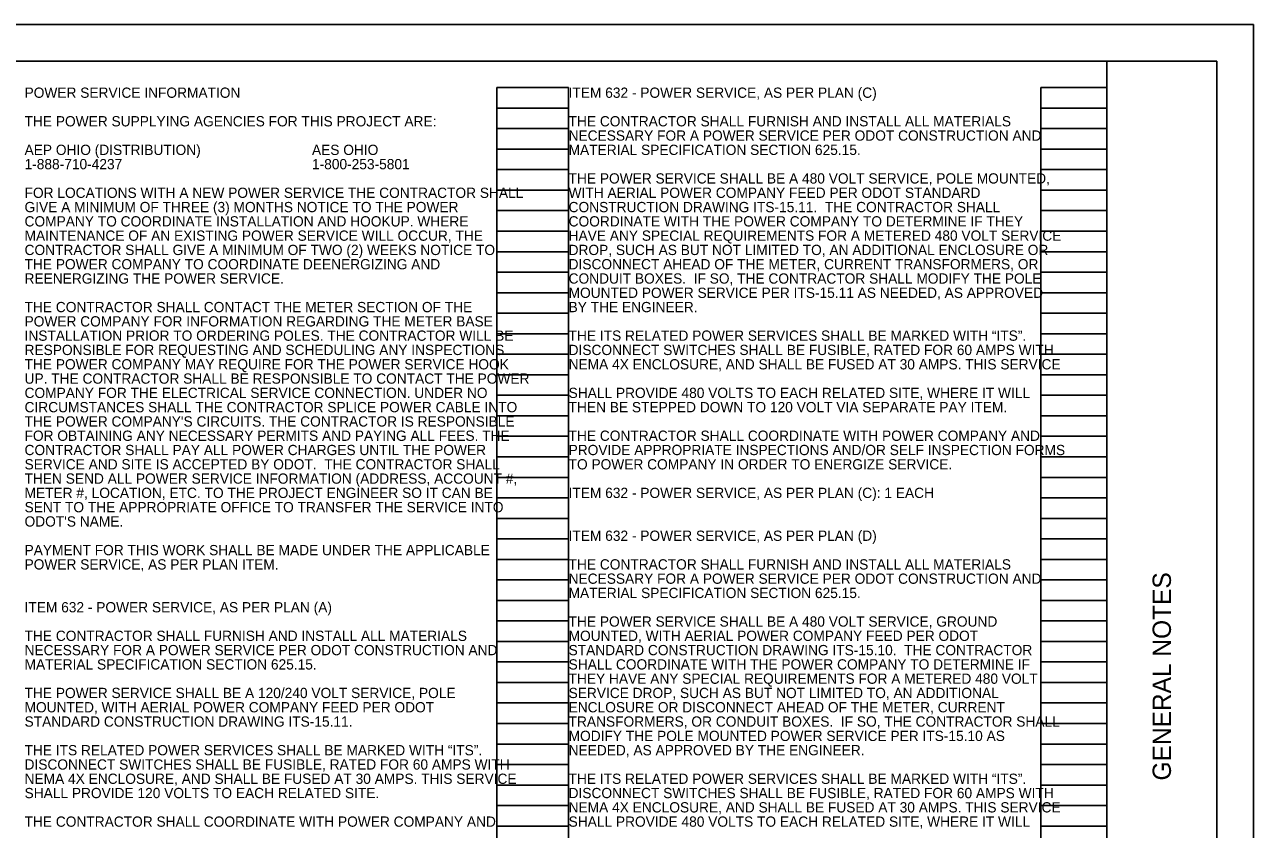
# Model space of a CAD drawing. Extents: x 0 to 34, y 0 to 22.
# Drawn here: x 17.24 to 34, y 11.01 to 22 of the extents above; entities that cross this region are included whole.
import ezdxf

# ---------------------------------------------------------------- set-up
doc = ezdxf.new("R2010")
doc.units = 0
for name, color, linetype in [('SH_Border', 7, 'Continuous'), ('SH_Cut_Line', 7, 'Continuous'), ('SH_Data', 7, 'Continuous'), ('SH_Text', 7, 'Continuous')]:
    doc.layers.add(name, color=color, linetype=linetype)

msp = doc.modelspace()

# ---------------------------------------------------------------- linework, layer by layer
at = {"layer": 'SH_Border'}
msp.add_line((32, 0.5), (32, 21.5), dxfattribs=at)
msp.add_lwpolyline([(1.5, 21.5), (33.5, 21.5), (33.5, 0.5), (1.5, 0.5)], close=True, dxfattribs=at)
at = {"layer": 'SH_Cut_Line'}
msp.add_lwpolyline([(0, 0), (34, 0), (34, 22), (0, 22)], close=True, dxfattribs=at)
at = {"layer": 'SH_Data'}
for p, q in [((23.68, 0.98), (23.68, 21.14)), ((23.68, 21.14), (24.66, 21.14)), ((24.66, 0.98), (24.66, 21.14)), ((31.1, 0.98), (31.1, 21.14)), ((31.1, 21.14), (32, 21.14)), ((32, 0.98), (32, 21.14)), ((23.68, 20.86), (24.66, 20.86)), ((31.1, 20.86), (32, 20.86)), ((23.68, 20.58), (24.66, 20.58)), ((31.1, 20.58), (32, 20.58)), ((23.68, 20.3), (24.66, 20.3)), ((31.1, 20.3), (32, 20.3)), ((23.68, 20.02), (24.66, 20.02)), ((31.1, 20.02), (32, 20.02)), ((23.68, 19.74), (24.66, 19.74)), ((31.1, 19.74), (32, 19.74)), ((23.68, 19.46), (24.66, 19.46)), ((31.1, 19.46), (32, 19.46)), ((23.68, 19.18), (24.66, 19.18)), ((31.1, 19.18), (32, 19.18)), ((23.68, 18.9), (24.66, 18.9)), ((31.1, 18.9), (32, 18.9)), ((23.68, 18.62), (24.66, 18.62)), ((31.1, 18.62), (32, 18.62)), ((23.68, 18.34), (24.66, 18.34)), ((31.1, 18.34), (32, 18.34)), ((23.68, 18.06), (24.66, 18.06)), ((31.1, 18.06), (32, 18.06)), ((23.68, 17.78), (24.66, 17.78)), ((31.1, 17.78), (32, 17.78)), ((23.68, 17.5), (24.66, 17.5)), ((31.1, 17.5), (32, 17.5)), ((23.68, 17.22), (24.66, 17.22)), ((31.1, 17.22), (32, 17.22)), ((23.68, 16.94), (24.66, 16.94)), ((31.1, 16.94), (32, 16.94)), ((23.68, 16.66), (24.66, 16.66)), ((31.1, 16.66), (32, 16.66)), ((23.68, 16.38), (24.66, 16.38)), ((31.1, 16.38), (32, 16.38)), ((23.68, 16.1), (24.66, 16.1)), ((31.1, 16.1), (32, 16.1)), ((23.68, 15.82), (24.66, 15.82)), ((31.1, 15.82), (32, 15.82)), ((23.68, 15.54), (24.66, 15.54)), ((31.1, 15.54), (32, 15.54)), ((23.68, 15.26), (24.66, 15.26)), ((31.1, 15.26), (32, 15.26)), ((23.68, 14.98), (24.66, 14.98)), ((31.1, 14.98), (32, 14.98)), ((23.68, 14.7), (24.66, 14.7)), ((31.1, 14.7), (32, 14.7)), ((23.68, 14.42), (24.66, 14.42)), ((31.1, 14.42), (32, 14.42)), ((23.68, 14.14), (24.66, 14.14)), ((31.1, 14.14), (32, 14.14)), ((23.68, 13.86), (24.66, 13.86)), ((31.1, 13.86), (32, 13.86)), ((23.68, 13.58), (24.66, 13.58)), ((31.1, 13.58), (32, 13.58)), ((23.68, 13.3), (24.66, 13.3)), ((31.1, 13.3), (32, 13.3)), ((23.68, 13.02), (24.66, 13.02)), ((31.1, 13.02), (32, 13.02)), ((23.68, 12.74), (24.66, 12.74)), ((31.1, 12.74), (32, 12.74)), ((23.68, 12.46), (24.66, 12.46)), ((31.1, 12.46), (32, 12.46)), ((23.68, 12.18), (24.66, 12.18)), ((31.1, 12.18), (32, 12.18)), ((23.68, 11.9), (24.66, 11.9)), ((31.1, 11.9), (32, 11.9)), ((23.68, 11.62), (24.66, 11.62)), ((31.1, 11.62), (32, 11.62)), ((23.68, 11.34), (24.66, 11.34)), ((31.1, 11.34), (32, 11.34)), ((23.68, 11.06), (24.66, 11.06)), ((31.1, 11.06), (32, 11.06))]:
    msp.add_line(p, q, dxfattribs=at)

# ---------------------------------------------------------------- texts
msp.add_text('GENERAL NOTES', height=0.25, rotation=90, dxfattribs=at).set_placement((32.875, 11.682))
at = {"layer": 'SH_Text'}
for s, p in [('POWER SERVICE INFORMATION', (17.24, 21)), ('ITEM 632 - POWER SERVICE, AS PER PLAN (C)', (24.66, 21)), ('THE POWER SUPPLYING AGENCIES FOR THIS PROJECT ARE:', (17.24, 20.61)), ('THE CONTRACTOR SHALL FURNISH AND INSTALL ALL MATERIALS ', (24.66, 20.61)), ('NECESSARY FOR A POWER SERVICE PER ODOT CONSTRUCTION AND ', (24.66, 20.415)), ('AEP OHIO (DISTRIBUTION)', (17.24, 20.22)), ('AES OHIO', (21.16, 20.22)), ('MATERIAL SPECIFICATION SECTION 625.15. ', (24.66, 20.22)), ('1-888-710-4237', (17.24, 20.025)), ('1-800-253-5801', (21.16, 20.025)), ('THE POWER SERVICE SHALL BE A 480 VOLT SERVICE, POLE MOUNTED, ', (24.66, 19.83)), ('FOR LOCATIONS WITH A NEW POWER SERVICE THE CONTRACTOR SHALL ', (17.24, 19.634)), ('WITH AERIAL POWER COMPANY FEED PER ODOT STANDARD ', (24.66, 19.634)), ('GIVE A MINIMUM OF THREE (3) MONTHS NOTICE TO THE POWER ', (17.24, 19.439)), ('CONSTRUCTION DRAWING ITS-15.11.  THE CONTRACTOR SHALL ', (24.66, 19.439)), ('COMPANY TO COORDINATE INSTALLATION AND HOOKUP. WHERE ', (17.24, 19.244)), ('COORDINATE WITH THE POWER COMPANY TO DETERMINE IF THEY ', (24.66, 19.244)), ('MAINTENANCE OF AN EXISTING POWER SERVICE WILL OCCUR, THE ', (17.24, 19.049)), ('HAVE ANY SPECIAL REQUIREMENTS FOR A METERED 480 VOLT SERVICE ', (24.66, 19.049)), ('CONTRACTOR SHALL GIVE A MINIMUM OF TWO (2) WEEKS NOTICE TO ', (17.24, 18.854)), ('DROP, SUCH AS BUT NOT LIMITED TO, AN ADDITIONAL ENCLOSURE OR ', (24.66, 18.854)), ('THE POWER COMPANY TO COORDINATE DEENERGIZING AND ', (17.24, 18.659)), ('DISCONNECT AHEAD OF THE METER, CURRENT TRANSFORMERS, OR ', (24.66, 18.659)), ('REENERGIZING THE POWER SERVICE.  ', (17.24, 18.464)), ('CONDUIT BOXES.  IF SO, THE CONTRACTOR SHALL MODIFY THE POLE ', (24.66, 18.464)), ('MOUNTED POWER SERVICE PER ITS-15.11 AS NEEDED, AS APPROVED ', (24.66, 18.269)), ('THE CONTRACTOR SHALL CONTACT THE METER SECTION OF THE ', (17.24, 18.074)), ('BY THE ENGINEER.', (24.66, 18.074)), ('POWER COMPANY FOR INFORMATION REGARDING THE METER BASE ', (17.24, 17.879)), ('INSTALLATION PRIOR TO ORDERING POLES. THE CONTRACTOR WILL BE ', (17.24, 17.684)), ('THE ITS RELATED POWER SERVICES SHALL BE MARKED WITH “ITS”. ', (24.66, 17.684)), ('RESPONSIBLE FOR REQUESTING AND SCHEDULING ANY INSPECTIONS ', (17.24, 17.489)), ('DISCONNECT SWITCHES SHALL BE FUSIBLE, RATED FOR 60 AMPS WITH ', (24.66, 17.489)), ('THE POWER COMPANY MAY REQUIRE FOR THE POWER SERVICE HOOK ', (17.24, 17.293)), ('NEMA 4X ENCLOSURE, AND SHALL BE FUSED AT 30 AMPS. THIS SERVICE ', (24.66, 17.293)), ('UP. THE CONTRACTOR SHALL BE RESPONSIBLE TO CONTACT THE POWER ', (17.24, 17.098)), ('COMPANY FOR THE ELECTRICAL SERVICE CONNECTION. UNDER NO ', (17.24, 16.903)), ('SHALL PROVIDE 480 VOLTS TO EACH RELATED SITE, WHERE IT WILL ', (24.66, 16.903)), ('CIRCUMSTANCES SHALL THE CONTRACTOR SPLICE POWER CABLE INTO ', (17.24, 16.708)), ('THEN BE STEPPED DOWN TO 120 VOLT VIA SEPARATE PAY ITEM.', (24.66, 16.708)), ("THE POWER COMPANY'S CIRCUITS. THE CONTRACTOR IS RESPONSIBLE ", (17.24, 16.513)), ('FOR OBTAINING ANY NECESSARY PERMITS AND PAYING ALL FEES. THE ', (17.24, 16.318)), ('THE CONTRACTOR SHALL COORDINATE WITH POWER COMPANY AND ', (24.66, 16.318)), ('CONTRACTOR SHALL PAY ALL POWER CHARGES UNTIL THE POWER ', (17.24, 16.123)), ('PROVIDE APPROPRIATE INSPECTIONS AND/OR SELF INSPECTION FORMS ', (24.66, 16.123)), ('SERVICE AND SITE IS ACCEPTED BY ODOT.  THE CONTRACTOR SHALL ', (17.24, 15.928)), ('TO POWER COMPANY IN ORDER TO ENERGIZE SERVICE.', (24.66, 15.928)), ('THEN SEND ALL POWER SERVICE INFORMATION (ADDRESS, ACCOUNT #, ', (17.24, 15.733)), ('METER #, LOCATION, ETC. TO THE PROJECT ENGINEER SO IT CAN BE ', (17.24, 15.538)), ('ITEM 632 - POWER SERVICE, AS PER PLAN (C): 1 EACH', (24.66, 15.538)), ('SENT TO THE APPROPRIATE OFFICE TO TRANSFER THE SERVICE INTO ', (17.24, 15.343)), ("ODOT'S NAME.", (17.24, 15.148)), ('ITEM 632 - POWER SERVICE, AS PER PLAN (D)', (24.66, 14.953)), ('PAYMENT FOR THIS WORK SHALL BE MADE UNDER THE APPLICABLE ', (17.24, 14.757)), ('POWER SERVICE, AS PER PLAN ITEM.', (17.24, 14.562)), ('THE CONTRACTOR SHALL FURNISH AND INSTALL ALL MATERIALS ', (24.66, 14.562)), ('NECESSARY FOR A POWER SERVICE PER ODOT CONSTRUCTION AND ', (24.66, 14.367)), ('MATERIAL SPECIFICATION SECTION 625.15. ', (24.66, 14.172)), ('ITEM 632 - POWER SERVICE, AS PER PLAN (A)', (17.24, 13.977)), ('THE POWER SERVICE SHALL BE A 480 VOLT SERVICE, GROUND ', (24.66, 13.782)), ('THE CONTRACTOR SHALL FURNISH AND INSTALL ALL MATERIALS ', (17.24, 13.587)), ('MOUNTED, WITH AERIAL POWER COMPANY FEED PER ODOT ', (24.66, 13.587)), ('NECESSARY FOR A POWER SERVICE PER ODOT CONSTRUCTION AND ', (17.24, 13.392)), ('STANDARD CONSTRUCTION DRAWING ITS-15.10.  THE CONTRACTOR ', (24.66, 13.392)), ('MATERIAL SPECIFICATION SECTION 625.15. ', (17.24, 13.197)), ('SHALL COORDINATE WITH THE POWER COMPANY TO DETERMINE IF ', (24.66, 13.197)), ('THEY HAVE ANY SPECIAL REQUIREMENTS FOR A METERED 480 VOLT ', (24.66, 13.002)), ('THE POWER SERVICE SHALL BE A 120/240 VOLT SERVICE, POLE ', (17.24, 12.807)), ('SERVICE DROP, SUCH AS BUT NOT LIMITED TO, AN ADDITIONAL ', (24.66, 12.807)), ('MOUNTED, WITH AERIAL POWER COMPANY FEED PER ODOT ', (17.24, 12.612)), ('ENCLOSURE OR DISCONNECT AHEAD OF THE METER, CURRENT ', (24.66, 12.612)), ('STANDARD CONSTRUCTION DRAWING ITS-15.11.', (17.24, 12.417)), ('TRANSFORMERS, OR CONDUIT BOXES.  IF SO, THE CONTRACTOR SHALL ', (24.66, 12.417)), ('MODIFY THE POLE MOUNTED POWER SERVICE PER ITS-15.10 AS ', (24.66, 12.221)), ('THE ITS RELATED POWER SERVICES SHALL BE MARKED WITH “ITS”. ', (17.24, 12.026)), ('NEEDED, AS APPROVED BY THE ENGINEER.', (24.66, 12.026)), ('DISCONNECT SWITCHES SHALL BE FUSIBLE, RATED FOR 60 AMPS WITH ', (17.24, 11.831)), ('NEMA 4X ENCLOSURE, AND SHALL BE FUSED AT 30 AMPS. THIS SERVICE ', (17.24, 11.636)), ('THE ITS RELATED POWER SERVICES SHALL BE MARKED WITH “ITS”. ', (24.66, 11.636)), ('SHALL PROVIDE 120 VOLTS TO EACH RELATED SITE.', (17.24, 11.441)), ('DISCONNECT SWITCHES SHALL BE FUSIBLE, RATED FOR 60 AMPS WITH ', (24.66, 11.441)), ('NEMA 4X ENCLOSURE, AND SHALL BE FUSED AT 30 AMPS. THIS SERVICE ', (24.66, 11.246)), ('THE CONTRACTOR SHALL COORDINATE WITH POWER COMPANY AND ', (17.24, 11.051)), ('SHALL PROVIDE 480 VOLTS TO EACH RELATED SITE, WHERE IT WILL ', (24.66, 11.051))]:
    msp.add_text(s, height=0.14, dxfattribs=at).set_placement(p)

doc.saveas('drawing.dxf')
